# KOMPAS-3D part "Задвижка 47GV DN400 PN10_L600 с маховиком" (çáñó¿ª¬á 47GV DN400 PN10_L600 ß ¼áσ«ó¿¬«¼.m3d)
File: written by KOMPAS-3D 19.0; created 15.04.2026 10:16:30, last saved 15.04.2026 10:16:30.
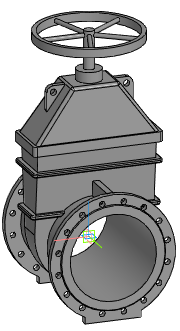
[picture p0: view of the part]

Document properties: Автор: Евгений; Полное имя файла: Z:\3.Личные\kachalov\3d для проектировщиков\2.1 Тип 47GV, 47GV.Z\Задвижка 47GV_DN40-DN600\stp_Задвижка 47GV\Задвижка 47GV DN400 PN10_L600 с маховиком.m3d

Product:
- Part/product: Задвижка 47GV DN400 PN10_L600 с маховиком

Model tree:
1. Операция без истории:1  (labels: Задвижка 47GV DN400 PN10_L600 с маховиком)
